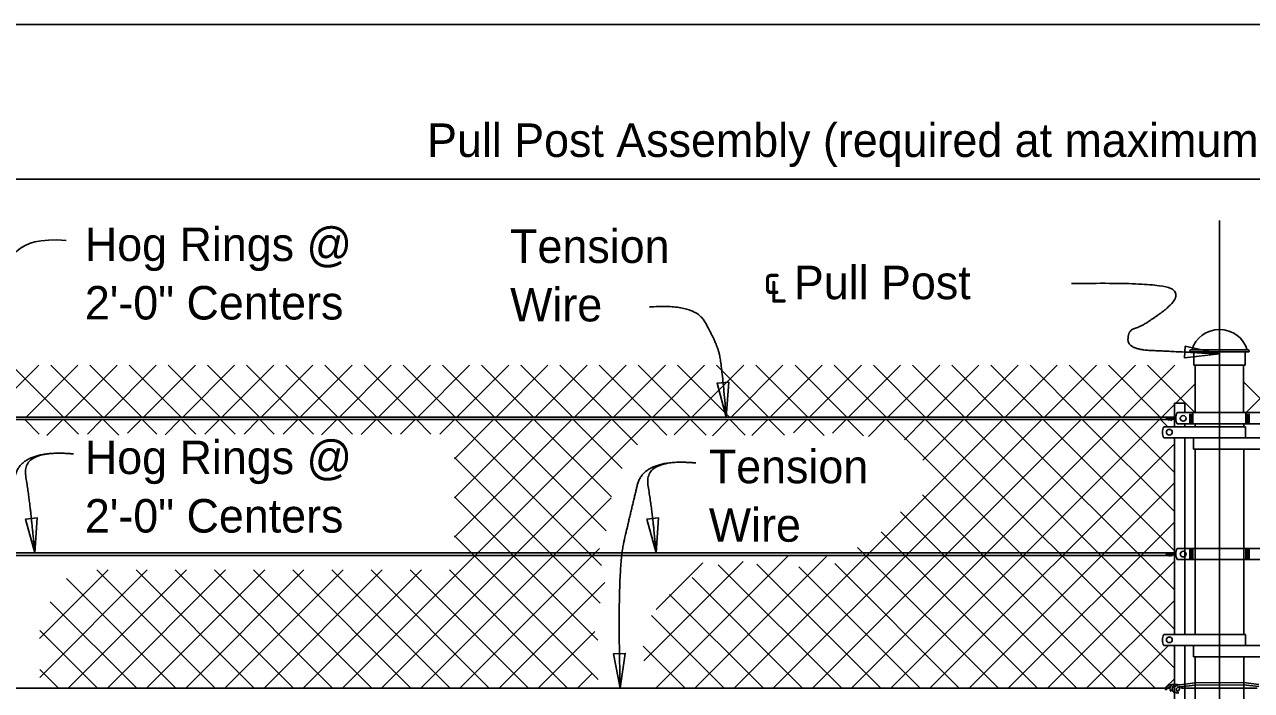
# Model space of a CAD drawing. Extents: x 0 to 41.1, y 0 to 26.4.
# Drawn here: x 5.02 to 12.4, y 22.39 to 26.4 of the extents above; entities that cross this region are included whole.
import ezdxf

# ---------------------------------------------------------------- set-up
doc = ezdxf.new("R2010")
doc.units = 0
for name, color, linetype in [('CL_Major', 7, 'Continuous'), ('Dimension', 7, 'Continuous'), ('Miscellaneous', 7, 'Continuous'), ('Miscellaneous1', 7, 'Continuous'), ('SteelMisc', 7, 'Continuous'), ('SteelMisc_h', 7, 'Continuous'), ('TextStructures', 7, 'Continuous')]:
    doc.layers.add(name, color=color, linetype=linetype)

msp = doc.modelspace()

# ---------------------------------------------------------------- linework, layer by layer
at = {"layer": 'CL_Major'}
msp.add_line((12.2062, 25.2199), (12.2062, 14.8548), dxfattribs=at)
at = {"layer": 'Dimension'}
msp.add_line((2.2062, 25.4682), (22.2062, 25.4682), dxfattribs=at)
for points in [[(12.2062, 24.4166), (12.0002, 24.4632), (11.9964, 24.3927)], [(9.238, 24.0366), (9.2538, 24.2472), (9.1835, 24.2406)], [(5.0788, 23.219), (5.0926, 23.4298), (5.0224, 23.4226)], [(8.8174, 23.219), (8.8313, 23.4298), (8.7611, 23.4226)], [(8.6004, 22.4048), (8.6312, 22.6137), (8.5607, 22.6122)]]:
    msp.add_lwpolyline(points, close=True, dxfattribs=at)
for points, degree in [([(5.2657, 25.0995), (4.9524, 25.1279), (4.8838, 24.8459), (4.8116, 24.5363), (4.8088, 24.0365)], 3), ([(11.3168, 24.8403), (11.8625, 24.8501), (11.985, 24.7612), (11.7408, 24.5799), (11.6559, 24.5616), (11.6559, 24.4437), (11.934, 24.4315), (12.2063, 24.4166)], 2), ([(8.7761, 24.6996), (9.0478, 24.722), (9.174, 24.4948), (9.2108, 24.3733), (9.238, 24.0365)], 2), ([(5.3115, 23.815), (4.9982, 23.8433), (4.9198, 23.5211), (4.8367, 23.1628), (4.8566, 22.4048)], 2), ([(5.3115, 23.815), (4.9982, 23.8433), (5.0481, 23.5211), (5.0667, 23.326), (5.0788, 23.219)], 2), ([(9.0561, 23.7607), (8.7428, 23.789), (8.6644, 23.4668), (8.5813, 23.1085), (8.6004, 22.4048)], 2), ([(9.0561, 23.7607), (8.7428, 23.789), (8.7927, 23.4668), (8.8113, 23.2717), (8.8174, 23.219)], 2)]:
    msp.add_open_spline(points, degree=degree, dxfattribs=at)
at = {"layer": 'Miscellaneous'}
for p, q in [((5.1017, 24.349), (4.7948, 24.0422)), ((5.2507, 24.0365), (4.9382, 24.349)), ((5.3374, 24.349), (5.0249, 24.0365)), ((5.4864, 24.0365), (5.1739, 24.349)), ((5.5731, 24.349), (5.2606, 24.0365)), ((5.7221, 24.0365), (5.4096, 24.349)), ((5.8088, 24.349), (5.4963, 24.0365)), ((5.9579, 24.0365), (5.6453, 24.349)), ((6.0445, 24.349), (5.732, 24.0365)), ((6.1936, 24.0365), (5.881, 24.349)), ((6.2802, 24.349), (5.9677, 24.0365)), ((6.4293, 24.0365), (6.1167, 24.349)), ((6.5159, 24.349), (6.2034, 24.0365)), ((6.665, 24.0365), (6.3524, 24.349)), ((6.7516, 24.349), (6.4391, 24.0365)), ((6.9007, 24.0365), (6.5881, 24.349)), ((6.9873, 24.349), (6.6748, 24.0365)), ((7.1364, 24.0365), (6.8238, 24.349)), ((7.223, 24.349), (6.9105, 24.0365)), ((7.3721, 24.0365), (7.0595, 24.349)), ((7.4587, 24.349), (7.1462, 24.0365)), ((7.6078, 24.0365), (7.2952, 24.349)), ((7.6944, 24.349), (7.3819, 24.0365)), ((7.8435, 24.0365), (7.5309, 24.349)), ((7.9301, 24.349), (7.6176, 24.0365)), ((8.0792, 24.0365), (7.7666, 24.349)), ((8.1658, 24.349), (7.8533, 24.0365)), ((8.3149, 24.0365), (8.0023, 24.349)), ((8.4015, 24.349), (8.089, 24.0365)), ((8.5506, 24.0365), (8.238, 24.349)), ((8.6372, 24.349), (8.3247, 24.0365)), ((8.7863, 24.0365), (8.4737, 24.349)), ((8.8729, 24.349), (8.5604, 24.0365)), ((9.022, 24.0365), (8.7094, 24.349)), ((9.1086, 24.349), (8.7961, 24.0365)), ((9.2577, 24.0365), (8.9451, 24.349)), ((9.3443, 24.349), (9.0318, 24.0365)), ((9.4934, 24.0365), (9.1808, 24.349)), ((9.58, 24.349), (9.2675, 24.0365)), ((9.7291, 24.0365), (9.4166, 24.349)), ((9.8157, 24.349), (9.5032, 24.0365)), ((9.9648, 24.0365), (9.6523, 24.349)), ((10.0514, 24.349), (9.7389, 24.0365)), ((10.2005, 24.0365), (9.888, 24.349)), ((10.2871, 24.349), (9.9746, 24.0365)), ((10.4362, 24.0365), (10.1237, 24.349)), ((10.5228, 24.349), (10.2103, 24.0365)), ((10.6719, 24.0365), (10.3594, 24.349)), ((10.7585, 24.349), (10.446, 24.0365)), ((10.9076, 24.0365), (10.5951, 24.349)), ((10.9942, 24.349), (10.6817, 24.0365)), ((11.1433, 24.0365), (10.8308, 24.349)), ((11.2299, 24.349), (10.9174, 24.0365)), ((11.379, 24.0365), (11.0665, 24.349)), ((11.4657, 24.349), (11.1531, 24.0365)), ((11.6147, 24.0365), (11.3022, 24.349)), ((11.7014, 24.349), (11.3888, 24.0365)), ((11.8504, 24.0365), (11.5379, 24.349)), ((11.9371, 24.349), (11.6245, 24.0365)), ((12.0603, 24.0623), (11.7736, 24.349)), ((12.3656, 24.0631), (12.6516, 24.349)), ((12.0603, 24.2366), (10.2285, 22.4048)), ((12.352, 24.2494), (12.5649, 24.0365)), ((5.1043, 23.9344), (5.017, 24.0218)), ((5.2458, 24.0218), (5.1507, 23.9266)), ((5.2458, 24.0218), (5.1585, 23.9344)), ((5.34, 23.9344), (5.2527, 24.0218)), ((5.4815, 24.0218), (5.3942, 23.9344)), ((5.5828, 23.9273), (5.4884, 24.0218)), ((5.7172, 24.0218), (5.6353, 23.9398)), ((5.8114, 23.9344), (5.7241, 24.0218)), ((5.9529, 24.0218), (5.8616, 23.9304)), ((6.0471, 23.9344), (5.9598, 24.0218)), ((6.1886, 24.0218), (6.1013, 23.9344)), ((6.2828, 23.9344), (6.1955, 24.0218)), ((6.4243, 24.0218), (6.337, 23.9344)), ((6.5185, 23.9344), (6.4312, 24.0218)), ((6.66, 24.0218), (6.5727, 23.9344)), ((6.7542, 23.9344), (6.6669, 24.0218)), ((6.8957, 24.0218), (6.8036, 23.9297)), ((6.9899, 23.9344), (6.9026, 24.0218)), ((8.5456, 24.0218), (6.9286, 22.4048)), ((7.1314, 24.0218), (7.0414, 23.9318)), ((7.2256, 23.9344), (7.1383, 24.0218)), ((8.7813, 24.0218), (7.1643, 22.4048)), ((7.3671, 24.0218), (7.2793, 23.9339)), ((7.4613, 23.9344), (7.374, 24.0218)), ((7.6028, 24.0218), (7.5155, 23.9344)), ((8.0742, 24.0218), (7.6029, 23.5504)), ((7.8385, 24.0218), (7.6029, 23.7861)), ((8.3099, 24.0218), (7.6029, 23.3147)), ((8.4874, 23.1441), (7.6097, 24.0218)), ((8.515, 23.3522), (7.8454, 24.0218)), ((8.5473, 23.5556), (8.0811, 24.0218)), ((8.6123, 23.7263), (8.3168, 24.0218)), ((8.7037, 23.8706), (8.5525, 24.0218)), ((8.8813, 23.9287), (8.7882, 24.0218)), ((9.017, 24.0218), (8.9244, 23.9291)), ((9.117, 23.9287), (9.0239, 24.0218)), ((9.2527, 24.0218), (9.1549, 23.9239)), ((9.3527, 23.9287), (9.2596, 24.0218)), ((9.4884, 24.0218), (9.3919, 23.9252)), ((9.5884, 23.9287), (9.4953, 24.0218)), ((9.7242, 24.0218), (9.6441, 23.9417)), ((9.8278, 23.925), (9.731, 24.0218)), ((11.3741, 24.0218), (9.7571, 22.4048)), ((9.9599, 24.0218), (9.877, 23.9389)), ((10.0639, 23.9246), (9.9668, 24.0218)), ((11.6098, 24.0218), (9.9928, 22.4048)), ((10.1956, 24.0218), (10.0944, 23.9206)), ((11.8195, 22.4048), (10.2025, 24.0218)), ((10.9027, 24.0218), (10.2239, 23.343)), ((10.4313, 24.0218), (10.3102, 23.9007)), ((10.667, 24.0218), (10.4218, 23.7766)), ((11.1384, 24.0218), (10.4313, 23.3147)), ((11.9353, 22.5246), (10.4382, 24.0218)), ((11.9353, 22.7603), (10.6739, 24.0218)), ((11.9353, 22.996), (10.9096, 24.0218)), ((11.9353, 23.2317), (11.1453, 24.0218)), ((11.9353, 23.4674), (11.381, 24.0218)), ((11.9353, 23.7031), (11.6167, 24.0218)), ((11.8956, 23.9786), (11.8524, 24.0218)), ((11.9353, 23.8759), (10.4642, 22.4048)), ((8.48, 22.9158), (7.6029, 23.7929)), ((11.9353, 23.6402), (10.6999, 22.4048)), ((8.4664, 22.6937), (7.6029, 23.5572)), ((11.5838, 22.4048), (10.42, 23.5685)), ((8.5456, 23.5503), (7.4, 22.4048)), ((11.348, 22.4048), (10.2867, 23.4661)), ((11.9353, 23.4045), (10.9356, 22.4048)), ((10.2239, 23.343), (9.2857, 22.4048)), ((11.1123, 22.4048), (10.1704, 23.3467)), ((8.4668, 22.4576), (7.6029, 23.3215)), ((10.4313, 23.3147), (9.5214, 22.4048)), ((8.4762, 23.2452), (7.6357, 22.4048)), ((9.615, 23.2055), (8.8143, 22.4048)), ((9.8417, 23.1965), (9.05, 22.4048)), ((10.8766, 22.4048), (10.0292, 23.2522)), ((5.5188, 23.1163), (5.1055, 22.7029)), ((5.7545, 23.1163), (5.1078, 22.4696)), ((5.9902, 23.1163), (5.2787, 22.4048)), ((6.1626, 22.4048), (5.4511, 23.1163)), ((6.2259, 23.1163), (5.5144, 22.4048)), ((6.3983, 22.4048), (5.6868, 23.1163)), ((6.4616, 23.1163), (5.7501, 22.4048)), ((6.634, 22.4048), (5.9225, 23.1163)), ((6.6973, 23.1163), (5.9858, 22.4048)), ((6.8697, 22.4048), (6.1582, 23.1163)), ((6.933, 23.1163), (6.2215, 22.4048)), ((7.1054, 22.4048), (6.3939, 23.1163)), ((7.1687, 23.1163), (6.4572, 22.4048)), ((7.3411, 22.4048), (6.6296, 23.1163)), ((7.4044, 23.1163), (6.6929, 22.4048)), ((7.5768, 22.4048), (6.8653, 23.1163)), ((7.8125, 22.4048), (7.101, 23.1163)), ((8.0482, 22.4048), (7.3367, 23.1163)), ((8.2839, 22.4048), (7.5724, 23.1163)), ((9.3401, 23.1663), (8.7428, 22.569)), ((9.0978, 23.1597), (8.8163, 22.8782)), ((9.9338, 22.4048), (9.1908, 23.1477)), ((10.1695, 22.4048), (9.4222, 23.1521)), ((10.4052, 22.4048), (9.6754, 23.1346)), ((10.6409, 22.4048), (9.8912, 23.1545)), ((11.9353, 23.1688), (11.1713, 22.4048)), ((5.9269, 22.4048), (5.2677, 23.064)), ((8.5075, 23.0408), (7.8714, 22.4048)), ((9.6981, 22.4048), (9.0326, 23.0703)), ((9.4624, 22.4048), (8.8976, 22.9695)), ((5.6912, 22.4048), (5.1708, 22.9251)), ((11.9353, 22.9331), (11.407, 22.4048)), ((9.2267, 22.4048), (8.7891, 22.8423)), ((5.4555, 22.4048), (5.1078, 22.7524)), ((8.4481, 22.7457), (8.1071, 22.4048)), ((8.991, 22.4048), (8.7382, 22.6576)), ((11.8989, 22.6609), (11.6427, 22.4048)), ((5.2198, 22.4048), (5.1078, 22.5167)), ((8.4312, 22.4931), (8.3429, 22.4048)), ((11.9353, 22.4617), (11.8784, 22.4048))]:
    msp.add_line(p, q, dxfattribs=at)
at = {"layer": 'Miscellaneous1'}
msp.add_lwpolyline([(0, 26.4), (41.0667, 26.4), (41.0667, 0), (0, 0)], close=True, dxfattribs=at)
at = {"layer": 'SteelMisc'}
for p, q in [((12.0339, 24.441), (12.3785, 24.441)), ((12.3785, 24.4288), (12.0339, 24.4288)), ((12.0521, 24.349), (12.0521, 24.4288)), ((12.3602, 24.349), (12.3602, 24.4288)), ((12.3602, 24.349), (12.0521, 24.349)), ((12.0603, 24.0636), (12.0603, 24.349)), ((12.352, 24.0636), (12.352, 24.349)), ((11.9353, 24.0396), (11.9353, 24.1198)), ((11.9978, 24.1198), (11.9353, 24.1198)), ((11.9978, 24.0636), (11.9978, 24.1198)), ((11.9243, 24.0218), (2.5005, 24.0218)), ((11.9229, 24.0365), (2.5271, 24.0365)), ((11.9443, 24.0207), (11.9107, 24.0264)), ((11.9439, 24.0255), (11.9141, 24.0304)), ((11.945, 24.0412), (11.9157, 24.0366)), ((11.9442, 24.0362), (11.9182, 24.0321)), ((11.9353, 24.0396), (11.9353, 23.9786)), ((11.9353, 24.0347), (11.9353, 24.0269)), ((12.362, 24.0637), (11.9522, 24.0637)), ((12.362, 23.9959), (11.9527, 23.9959)), ((11.9978, 23.9959), (11.9978, 23.9786)), ((12.0236, 24.0528), (12.0466, 24.0528)), ((12.0236, 24.0473), (12.0466, 24.0473)), ((12.0236, 24.0393), (12.0466, 24.0393)), ((12.0236, 24.0337), (12.0466, 24.0337)), ((12.0236, 24.0257), (12.0466, 24.0257)), ((12.0236, 24.0202), (12.0466, 24.0202)), ((12.0236, 24.0122), (12.0466, 24.0122)), ((12.0236, 24.0066), (12.0466, 24.0066)), ((12.0466, 23.9959), (12.0466, 24.0637)), ((12.0505, 24.0637), (12.4602, 24.0637)), ((12.0505, 23.9959), (12.4598, 23.9959)), ((12.0604, 23.9786), (12.0604, 23.9959)), ((12.3521, 23.9786), (12.3521, 23.9959)), ((12.3886, 24.0528), (12.3657, 24.0528)), ((12.3886, 24.0473), (12.3657, 24.0473)), ((12.3886, 24.0393), (12.3657, 24.0393)), ((12.3886, 24.0337), (12.3657, 24.0337)), ((12.3886, 24.0257), (12.3657, 24.0257)), ((12.3886, 24.0202), (12.3657, 24.0202)), ((12.3886, 24.0122), (12.3657, 24.0122)), ((12.3886, 24.0066), (12.3657, 24.0066)), ((12.3658, 23.9959), (12.3658, 24.0637)), ((12.3621, 23.9786), (11.8709, 23.9786)), ((12.3621, 23.9786), (12.3621, 23.9109)), ((12.3621, 23.9109), (11.8717, 23.9109)), ((11.9353, 23.9109), (11.9353, 22.7286)), ((11.9978, 23.9109), (11.9978, 22.7286)), ((12.0505, 23.9109), (12.0505, 23.8433)), ((12.0505, 23.9109), (12.5416, 23.9109)), ((12.0505, 23.8433), (12.5408, 23.8433)), ((12.0604, 22.7286), (12.0604, 23.8433)), ((12.3521, 22.7286), (12.3521, 23.8433)), ((11.9244, 23.2043), (2.5006, 23.2043)), ((11.9231, 23.219), (2.5273, 23.219)), ((11.9445, 23.2033), (11.9109, 23.2089)), ((11.9441, 23.2081), (11.9143, 23.213)), ((11.9451, 23.2237), (11.9159, 23.2191)), ((11.9444, 23.2187), (11.9184, 23.2146)), ((11.9354, 23.2172), (11.9354, 23.2094)), ((12.3622, 23.2462), (11.9524, 23.2462)), ((12.0238, 23.2354), (12.0468, 23.2354)), ((12.0238, 23.2298), (12.0468, 23.2298)), ((12.0238, 23.2218), (12.0468, 23.2218)), ((12.0238, 23.2163), (12.0468, 23.2163)), ((12.0238, 23.2083), (12.0468, 23.2083)), ((12.0238, 23.2027), (12.0468, 23.2027)), ((12.0238, 23.1947), (12.0468, 23.1947)), ((12.0238, 23.1892), (12.0468, 23.1892)), ((12.0468, 23.1785), (12.0468, 23.2462)), ((12.0506, 23.2462), (12.4603, 23.2462)), ((12.3888, 23.2354), (12.3658, 23.2354)), ((12.3888, 23.2298), (12.3658, 23.2298)), ((12.3888, 23.2218), (12.3658, 23.2218)), ((12.3888, 23.2163), (12.3658, 23.2163)), ((12.3888, 23.2083), (12.3658, 23.2083)), ((12.3888, 23.2027), (12.3658, 23.2027)), ((12.3888, 23.1947), (12.3658, 23.1947)), ((12.3888, 23.1892), (12.3658, 23.1892)), ((12.366, 23.1785), (12.366, 23.2462)), ((12.3622, 23.1785), (11.9528, 23.1785)), ((12.0506, 23.1785), (12.46, 23.1785)), ((12.3621, 22.7286), (11.8709, 22.7286)), ((12.3621, 22.7286), (12.3621, 22.6609)), ((12.3621, 22.6609), (11.8717, 22.6609)), ((11.9353, 21.4785), (11.9353, 22.6609)), ((11.9978, 21.4785), (11.9978, 22.6609)), ((12.0505, 22.6609), (12.0505, 22.5933)), ((12.0505, 22.6609), (12.5416, 22.6609)), ((12.0505, 22.5933), (12.5408, 22.5933)), ((12.0604, 21.4785), (12.0604, 22.5933)), ((12.3521, 21.4785), (12.3521, 22.5933)), ((2.5108, 22.4048), (11.8852, 22.4048)), ((11.8951, 22.4048), (11.9083, 22.4048)), ((12.0603, 22.4374), (11.9675, 22.4257)), ((12.0603, 22.4229), (11.9675, 22.4132)), ((11.9782, 22.4048), (12.0603, 22.4048)), ((12.0603, 22.4374), (12.3515, 22.4391)), ((12.0603, 22.4229), (12.3515, 22.4245)), ((12.3515, 22.4391), (12.4435, 22.4275)), ((12.3515, 22.4245), (12.4434, 22.415)), ((12.352, 22.4048), (12.4324, 22.4048))]:
    msp.add_line(p, q, dxfattribs=at)
for centre, start, end in [((12.034, 24.4347), 91.1647, 268.8353), ((12.3783, 24.4347), 271.1647, 88.8353)]:
    msp.add_arc(centre, 0.00613, start, end, dxfattribs=at)
for centre, major_axis, ratio, start_param, end_param in [((12.2068, 24.4), (0.1711, 0), 0.957868, 0.252602, 2.888574), ((11.908, 24.0082), (-0.0274, 0), 0.957868, 5.133531, 5.654664), ((11.9, 24.0233), (0.0142, 0), 0.957868, 1.486836, 3.141593), ((11.9052, 24.0278), (-0.00944, 0), 0.957868, 6.009018, 8.249874), ((11.9048, 24.0288), (0.00872, 0), 0.957868, 1.29026, 2.959852), ((11.9048, 24.0288), (0.00503, 0), 0.92697, 1.570796, 4.502291), ((11.9113, 24.0283), (0.00872, 0), 0.957868, 1.29026, 4.182385), ((11.917, 24.0274), (-0.0115, -0.0041), 0.737732, 4.35367, 7.47816), ((11.9157, 24.0259), (-0.00527, 0), 0.957868, 5.22362, 7.507542), ((11.9136, 24.025), (-0.00301, 0), 0.957868, 6.141288, 6.278592), ((11.9189, 24.0225), (-0.00982, 0), 0.957868, 4.777514, 5.62749), ((11.9136, 24.025), (-0.00301, 0), 0.957868, 1.11255, 2.999696), ((11.9129, 24.0272), (0.00453, 0), 0.957868, 0.731188, 1.133458), ((11.913, 24.0267), (0.0095, 0), 0.957868, 5.011765, 6.030719), ((11.913, 24.0267), (0.0095, 0), 0.957868, 0.230606, 0.609214), ((12.0215, 24.03), (-0.0776, 0), 0.957868, 5.81433, 6.762456), ((11.9404, 23.9454), (-0.0776, 0), 0.957868, 5.821213, 6.765127), ((11.9082, 23.1908), (-0.0274, 0), 0.957868, 5.133531, 5.654664), ((11.9002, 23.2058), (0.0142, 0), 0.957868, 1.486836, 3.141593), ((11.9054, 23.2104), (-0.00944, 0), 0.957868, 6.009018, 8.249874), ((11.9049, 23.2113), (0.00872, 0), 0.957868, 1.29026, 2.959852), ((11.9049, 23.2113), (0.00503, 0), 0.92697, 1.570796, 4.502291), ((11.9115, 23.2108), (0.00872, 0), 0.957868, 1.29026, 4.182385), ((11.9172, 23.2099), (-0.0115, -0.0041), 0.737732, 4.35367, 7.47816), ((11.9159, 23.2084), (-0.00527, 0), 0.957868, 5.22362, 7.507542), ((11.9138, 23.2075), (-0.00301, 0), 0.957868, 6.141288, 6.278592), ((11.9191, 23.205), (-0.00982, 0), 0.957868, 4.777514, 5.62749), ((11.9138, 23.2075), (-0.00301, 0), 0.957868, 1.11255, 2.999696), ((11.9131, 23.2097), (0.00453, 0), 0.957868, 0.731188, 1.133458), ((11.9132, 23.2092), (0.0095, 0), 0.957868, 5.011765, 6.030719), ((11.9132, 23.2092), (0.0095, 0), 0.957868, 0.230606, 0.609214), ((12.0216, 23.2125), (-0.0776, 0), 0.957868, 5.81433, 6.762456), ((11.9404, 22.6954), (-0.0776, 0), 0.957868, 5.821213, 6.765127), ((11.9194, 22.3905), (0.0373, 0), 0.957868, 1.427863, 3.108042), ((11.9405, 22.3508), (-0.0724, 0), 0.957868, 5.133134, 5.652106), ((11.9331, 22.4025), (-0.0249, 0), 0.957868, 5.913851, 7.104804), ((11.9319, 22.405), (0.023, 0), 0.957868, 1.234085, 2.861055), ((11.9507, 22.3996), (0.0295, 0), 0.957868, 1.132635, 3.996184), ((11.9641, 22.4014), (-0.0303, -0.0108), 0.724765, 4.35367, 6.224248), ((11.954, 22.3928), (0.0206, -0.0021), 0.798607, 3.319436, 5.220153), ((11.9608, 22.3973), (-0.0139, 0), 0.957868, 5.822914, 6.485782), ((11.9552, 22.3949), (-0.00795, 0), 0.957868, 0.039428, 2.999692), ((11.9692, 22.3885), (-0.0259, 0), 0.957868, 4.777514, 5.646371), ((11.9535, 22.4007), (0.0119, 0), 0.957868, 5.725876, 7.416677), ((11.9535, 22.4007), (0.0119, 0), 0.957868, 5.639684, 5.723117), ((11.9537, 22.3995), (0.0251, 0), 0.957868, 0.221743, 0.642584)]:
    msp.add_ellipse(centre, major_axis=major_axis, ratio=ratio, start_param=start_param, end_param=end_param, dxfattribs=at)
for centre, major_axis in [((11.9881, 24.0291), (0.0178, 0)), ((11.9045, 23.9458), (0.0177, 0)), ((11.9883, 23.2117), (0.0178, 0)), ((11.9045, 22.6958), (0.0177, 0))]:
    msp.add_ellipse(centre, major_axis=major_axis, ratio=0.957868, dxfattribs=at)
at = {"layer": 'SteelMisc_h'}
msp.add_line((12.0603, 22.4048), (12.352, 22.4048), dxfattribs=at)

# ---------------------------------------------------------------- texts
at = {"layer": 'Dimension'}
for s, p in [('Hog Rings @ ', (5.3791, 24.9762)), ('Tension ', (7.9381, 24.9647)), ('2\'-0" Centers', (5.3791, 24.6242)), ('Wire ', (7.9381, 24.6127)), ('Hog Rings @ ', (5.3792, 23.6935)), ('Tension ', (9.1338, 23.6384)), ('2\'-0" Centers', (5.3792, 23.3415)), ('Wire ', (9.1338, 23.2864))]:
    msp.add_text(s, height=0.2016, dxfattribs=at).set_placement(p)
at = {"layer": 'TextStructures'}
for s, p in [('Pull Post Assembly (required at maximum intervals of 500\'-0")', (7.4383, 25.603)), ('℄ Pull Post', (9.4613, 24.7464))]:
    msp.add_text(s, height=0.2016, dxfattribs=at).set_placement(p)

doc.saveas('drawing.dxf')
